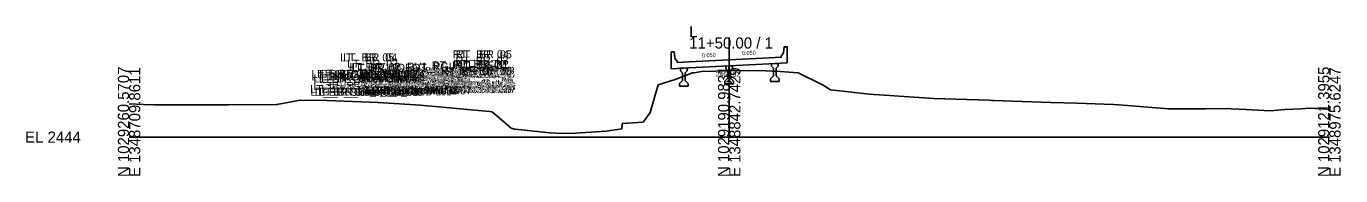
# Model space of a CAD drawing. Extents: x -26 to 1453, y -10 to 4527.
# Drawn here: x -25.7 to 302.8, y 1490.3 to 1527.8 of the extents above; entities that cross this region are included whole.
import ezdxf

# ---------------------------------------------------------------- set-up
doc = ezdxf.new("R2010")
doc.units = 0
for name, color, linetype in [('Default', 7, 'Continuous'), ('Exist Cross Section Cell', 7, 'Continuous'), ('Exist XS Center Line Elevation Label', 7, 'Continuous'), ('Exist XS Ground Line', 7, 'Continuous'), ('Prop CMT Concrete Structures', 7, 'Continuous'), ('Prop XS SE Text', 7, 'Continuous')]:
    doc.layers.add(name, color=color, linetype=linetype)

msp = doc.modelspace()

# ---------------------------------------------------------------- linework, layer by layer
at = {"layer": 'Exist Cross Section Cell'}
for p, q in [((150, 1500), (150, 1525.01)), ((0, 1500), (150, 1500)), ((150, 1500), (300, 1500))]:
    msp.add_line(p, q, dxfattribs=at)
at = {"layer": 'Exist XS Ground Line'}
msp.add_lwpolyline([(0, 1508.34), (3.62, 1508.21), (6.27, 1508.11), (8.42, 1508.1), (13.21, 1508.12), (24.83, 1508.11), (36.99, 1508.22), (37.28, 1508.23), (37.4, 1508.23), (41.41, 1509.03), (42.84, 1509.27), (49.41, 1509.21), (60.16, 1508.8), (62.22, 1508.65), (72.87, 1507.99), (74.46, 1507.87), (75.63, 1507.79), (79.15, 1507.46), (83.64, 1507.03), (90.05, 1506.45), (90.65, 1506.38), (91.35, 1505.82), (95.48, 1502.27), (96.38, 1501.97), (105.14, 1501.07), (108.09, 1500.88), (111.54, 1500.96), (119.21, 1501.53), (123.14, 1502.05), (123.21, 1503.37), (123.35, 1503.48), (124.11, 1503.46), (124.5, 1503.5), (124.6, 1503.47), (128.5, 1503.77), (128.53, 1503.77), (128.58, 1503.81), (130.28, 1506.2), (132.28, 1513.11), (136.51, 1514.44), (140.37, 1515.93), (140.74, 1516.11), (141.22, 1516.15), (143.1, 1516.42), (146.54, 1516.5), (150, 1516.62), (151.75, 1516.67), (159.16, 1516.59), (160.77, 1516.58), (162.73, 1516.44), (167.27, 1516.16), (173.29, 1513.13), (175.29, 1511.89), (185.06, 1510.77), (186.16, 1510.67), (187.55, 1510.62), (201.18, 1509.72), (214.97, 1509.24), (215.52, 1509.22), (216.03, 1509.2), (230.41, 1508.65), (236.88, 1508.49), (246.08, 1508.18), (247.3, 1508.08), (249.52, 1507.92), (259.77, 1507.08), (269.02, 1507.08), (274.93, 1507.16), (275.42, 1507.1), (279.21, 1506.94), (285.18, 1506.6), (288.87, 1506.94), (292.92, 1507.11), (295, 1507.24), (296.41, 1507.2), (297.17, 1507.15), (300, 1506.92)], dxfattribs=at)
at = {"layer": 'Prop CMT Concrete Structures'}
for points in [[(150, 1519.37), (140, 1518.87), (137, 1518.72), (136.99, 1518.97), (136.41, 1519.8), (136.24, 1521.38), (135.5, 1521.38), (135.5, 1517.14)], [(150, 1519.37), (160, 1519.87), (163, 1520.02), (163.01, 1520.27), (163.59, 1521.1), (163.76, 1522.68), (164.5, 1522.68), (164.5, 1518.59)], [(135.5, 1517.14), (140, 1517.37), (150, 1517.87)], [(150, 1517.87), (149.17, 1517.82)], [(149.17, 1517.82), (149.17, 1517.2)], [(150, 1517.87), (150, 1519.37)], [(150, 1517.87), (150, 1519.37)], [(164.5, 1518.59), (160, 1518.37), (150, 1517.87)], [(150, 1517.87), (150.83, 1517.91)], [(150, 1513.37), (150, 1517.87)], [(150, 1513.37), (150, 1517.87)], [(150.83, 1517.91), (150.83, 1517.2)], [(160.54, 1518.39), (161.38, 1518.43), (162.21, 1518.48)], [(160.54, 1517.77), (160.54, 1518.39)], [(162.21, 1518.48), (162.21, 1517.77)], [(139.46, 1517.34), (138.62, 1517.3), (137.79, 1517.26)], [(137.79, 1517.26), (137.79, 1516.63)], [(137.79, 1516.63), (138.29, 1516.13)], [(138.29, 1516.13), (138.29, 1514.21)], [(138.96, 1516.13), (139.46, 1516.63)], [(138.96, 1514.21), (138.96, 1516.13)], [(139.46, 1516.63), (139.46, 1517.34)], [(149.67, 1514.78), (148.92, 1514.03)], [(149.17, 1517.2), (149.67, 1516.7)], [(149.67, 1516.7), (149.67, 1514.78)], [(150.83, 1517.2), (150.33, 1516.7)], [(150.33, 1516.7), (150.33, 1514.78)], [(150.33, 1514.78), (151.08, 1514.03)], [(160.29, 1514.6), (161.04, 1515.35)], [(160.29, 1513.93), (160.29, 1514.6)], [(161.04, 1517.27), (160.54, 1517.77)], [(161.04, 1515.35), (161.04, 1517.27)], [(162.21, 1517.77), (161.71, 1517.27)], [(161.71, 1517.27), (161.71, 1515.35)], [(161.71, 1515.35), (162.46, 1514.6)], [(162.46, 1514.6), (162.46, 1513.93)], [(138.29, 1514.21), (137.54, 1513.46)], [(137.54, 1513.46), (137.54, 1512.8)], [(137.54, 1512.8), (138.62, 1512.8), (139.71, 1512.8)], [(139.71, 1513.46), (138.96, 1514.21)], [(139.71, 1512.8), (139.71, 1513.46)], [(148.92, 1514.03), (148.92, 1513.37)], [(148.92, 1513.37), (150, 1513.37)], [(151.08, 1513.37), (150, 1513.37)], [(151.08, 1514.03), (151.08, 1513.37)], [(162.46, 1513.93), (161.38, 1513.93), (160.29, 1513.93)]]:
    msp.add_lwpolyline(points, dxfattribs=at)

# ---------------------------------------------------------------- texts
at = {"layer": 'Default'}
for s, height, p in [('RT_ BR_04', 2, (80.95, 1519.77)), ('RT_ BR_05', 2, (81.69, 1519.77)), ('LT_ BR_05', 2, (52.74, 1518.99)), ('LT_ BR_04', 2, (53.48, 1518.99)), ('LT_BR_03', 2, (54.46, 1517.41)), ('LT_BR_02', 2, (55.05, 1516.57)), ('LT_BR_01', 2, (55.62, 1516.32)), ('LT_PV1_OEOT', 2, (55.74, 1516.41)), ('PV1_PGL', 2, (69.47, 1516.71)), ('RT_PV1_OEOT', 2, (75.69, 1517.01)), ('RT_BR_02', 2, (81.02, 1517.35)), ('RT_BR_01', 2, (81.57, 1517.1)), ('RT_BR_03', 2, (81.6, 1518.19)), ('LT_BR_Girder Out 02', 2, (45.58, 1514.85)), ('LT_BR_Girder Out 03', 2, (45.58, 1514.21)), ('LT_BR_Girder Out 04', 2, (46.08, 1513.71)), ('LT_BR_Girder Out 01', 2, (46.98, 1514.87)), ('LT_BR_Girder Out 12', 2, (47.39, 1513.71)), ('LT_BR_Girder Out 14', 2, (47.89, 1514.9)), ('LT_BR_Girder Out 13', 2, (47.89, 1514.21)), ('LT_BR_06', 2, (53.51, 1514.78)), ('LT_BR_Girder Mid 02', 2, (57.35, 1515.19)), ('LT_BR_Girder Mid 03', 2, (57.35, 1514.55)), ('LT_BR_Girder Mid 04', 2, (57.85, 1514.05)), ('LT_BR_07', 2, (58.06, 1514.91)), ('RT_BR_Girder Mid 04', 2, (58.47, 1514.05)), ('RT_BR_Girder Mid 02', 2, (58.97, 1515.24)), ('RT_BR_Girder Mid 03', 2, (58.97, 1514.55)), ('RT_BR_Girder Out 14', 2, (68.93, 1515.53)), ('RT_BR_Girder Out 13', 2, (68.93, 1514.89)), ('RT_BR_Girder Out 12', 2, (69.43, 1514.39)), ('RT_BR_Girder Out 04', 2, (69.45, 1514.39)), ('RT_BR_Girder Out 05', 2, (69.45, 1512.47)), ('RT_BR_Girder Out 01', 2, (69.68, 1515.55)), ('BR_PGL', 2, (69.83, 1515.21)), ('RT_BR_Girder Out 02', 2, (69.95, 1515.58)), ('RT_BR_Girder Out 03', 2, (69.95, 1514.89)), ('RT_BR_Girder Out 11', 2, (70, 1512.47)), ('RT_BR_07', 2, (78.01, 1515.51)), ('RT_BR_06', 2, (82.46, 1515.65)), ('LT_BR_Girder Out 06', 2, (45.28, 1511.04)), ('LT_BR_Girder Out 07', 2, (45.33, 1510.37)), ('LT_BR_Girder Out 05', 2, (46.08, 1511.79)), ('LT_BR_Girder Out 08', 2, (46.41, 1510.37)), ('LT_BR_Girder Out 09', 2, (47.49, 1510.37)), ('LT_BR_Girder Out 11', 2, (47.96, 1511.79)), ('LT_BR_Girder Out 10', 2, (48.06, 1511.04)), ('LT_BR_Girder Mid 06', 2, (57.05, 1511.38)), ('LT_BR_Girder Mid 07', 2, (57.1, 1510.71)), ('LT_BR_Girder Mid 05', 2, (57.85, 1512.13)), ('RT_BR_Girder Mid 05', 2, (58.47, 1512.13)), ('RT_BR_Girder Mid 06', 2, (59.17, 1511.38)), ('RT_BR_Girder Mid 07', 2, (59.22, 1510.71)), ('BR_Girder Mid 08', 2, (60.87, 1510.71)), ('RT_BR_Girder Out 09', 2, (68.03, 1511.05)), ('RT_BR_Girder Out 10', 2, (68.6, 1511.72)), ('RT_BR_Girder Out 08', 2, (69.12, 1511.05)), ('RT_BR_Girder Out 06', 2, (70.15, 1511.72)), ('RT_BR_Girder Out 07', 2, (70.2, 1511.05)), ('-', 0.0001, (0, 1500)), ('-', 0.0001, (0, 1500)), ('-', 0.0001, (0, 1500)), ('-', 0.0001, (0, 1500))]:
    msp.add_text(s, height=height, dxfattribs=at).set_placement(p)
at = {"layer": 'Exist Cross Section Cell'}
for s, p in [('L', (140, 1525.01)), ('11+50.00 / 1', (140, 1522.21)), ('EL 2444', (-26, 1498.6))]:
    msp.add_text(s, height=2.8, dxfattribs=at).set_placement(p)
for s, p in [('N 1029260.5707', (0, 1490)), ('E 1348709.8611', (2.8, 1490)), ('N 1029190.9831', (150, 1490)), ('E 1348842.7429', (152.8, 1490)), ('N 1029121.3955', (300, 1490)), ('E 1348975.6247', (302.8, 1490))]:
    msp.add_text(s, height=2.8, rotation=90, dxfattribs=at).set_placement(p)
at = {"layer": 'Exist XS Center Line Elevation Label'}
msp.add_text('2460.62', height=1.23, dxfattribs=at).set_placement((146.61, 1515.12))
at = {"layer": 'Prop XS SE Text'}
for p in [(143.2, 1519.98), (153.2, 1520.53)]:
    msp.add_text('0.050', height=1, rotation=2.8624, dxfattribs=at).set_placement(p)

doc.saveas('drawing.dxf')
